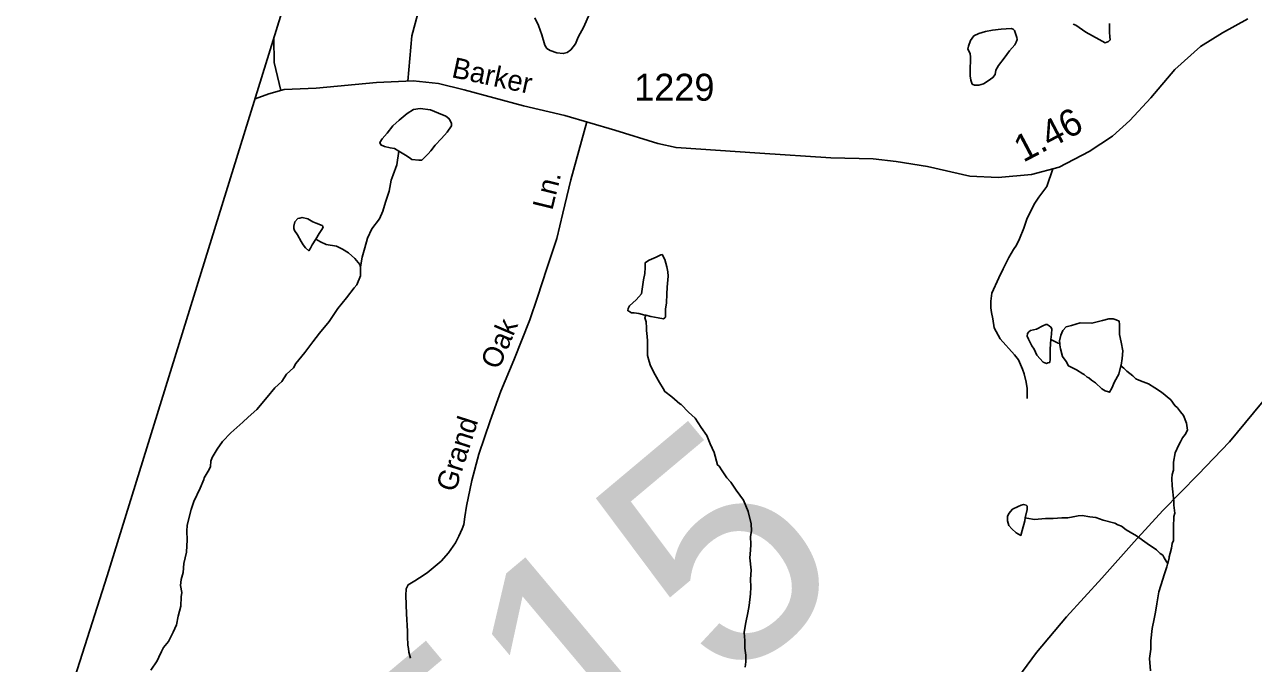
# Model space of a CAD drawing. Extents: x 2001466 to 2224147, y 644118 to 847247.
# Drawn here: x 2010030 to 2015726, y 706438 to 709402 of the extents above; entities that cross this region are included whole.
import ezdxf

# ---------------------------------------------------------------- set-up
doc = ezdxf.new("R2010")
doc.units = 0
for name, color, linetype in [('Exist Boundary Political CountyLine', 7, 'Continuous'), ('Exist Hydrographic Misc Water Feature', 7, 'Continuous'), ('Exist Railroad Mainline', 7, 'Continuous'), ('Exist Road Non-System Type 51', 7, 'Continuous'), ('Exist Road Non-System Type 51 Label', 7, 'Continuous'), ('Exist Road Primary US Structure RailRoad Number Label', 7, 'Continuous'), ('Exist Road Secondary Mileage Hundredths English Label', 7, 'Continuous'), ('Exist Road Secondary Type 51 Attributed', 7, 'Continuous'), ('Exist Road Secondary Type 51 Label', 7, 'Continuous'), ('Exist Road Secondary Type 51 Number Label', 7, 'Continuous')]:
    doc.layers.add(name, color=color, linetype=linetype)

msp = doc.modelspace()

# ---------------------------------------------------------------- linework, layer by layer
at = {"layer": 'Exist Boundary Political CountyLine'}
msp.add_lwpolyline([(2006817.6, 695750.4), (2007499.4, 697710.6), (2010412.6, 706844.6), (2011918.3, 711705.5), (2013748.8, 717730), (2014941.8, 722041.3), (2015284.7, 723238.9), (2015749.8, 724659.3), (2016152.8, 726117.8), (2016501.7, 727373.6), (2016860.6, 728619.5), (2017411.9, 730567.4), (2017756.8, 731851.4), (2018083.6, 732956.8), (2018350.2, 733869.6), (2018833.4, 735584.8), (2018918.2, 735898.3), (2019734.3, 740137.7), (2020502.6, 744108.1), (2021805.5, 746807.9), (2022821.6, 749625), (2023527, 751602.5)], dxfattribs=at)
at = {"layer": 'Exist Hydrographic Misc Water Feature'}
for points in [[(2012394.5, 709432.7), (2012412.5, 709396.7), (2012426.7, 709354.7), (2012440.6, 709306.7), (2012450.7, 709290.7), (2012466.7, 709280.7), (2012496.6, 709270.7), (2012526.7, 709266.7), (2012544.6, 709272.7), (2012562.6, 709284.7), (2012582.7, 709312.8), (2012596.5, 709342.8), (2012622.5, 709390.8), (2012648.5, 709450.8)], [(2014414.4, 709227.9), (2014414.4, 709249.9), (2014412.4, 709267.9), (2014402.3, 709287.9), (2014404.4, 709301.9), (2014414.4, 709327.9), (2014430.4, 709349.9), (2014452.4, 709359.9), (2014484.4, 709370), (2014516.4, 709376), (2014556.3, 709380), (2014602.3, 709384), (2014612.3, 709380), (2014618.3, 709374), (2014624.2, 709356), (2014628.3, 709342.1), (2014630.2, 709332.1), (2014626.5, 709320.1), (2014620.3, 709308.1), (2014594.5, 709280.1), (2014570.3, 709246), (2014544.4, 709212), (2014532.3, 709190), (2014528.5, 709170), (2014518.4, 709156), (2014496.5, 709140), (2014474.5, 709126), (2014452.6, 709120), (2014432.5, 709119.9), (2014422.4, 709125.9), (2014416.5, 709143.9), (2014412.4, 709163.9), (2014412.4, 709181.9), (2014412.4, 709205.9), (2014414.4, 709227.9)], [(2015058.3, 709406.3), (2015058.3, 709380.3), (2015058.3, 709366.3), (2015060.4, 709344.3), (2015062.2, 709330.3), (2015054.2, 709322.3), (2015038.2, 709316.3), (2015010.3, 709332.3), (2014948.2, 709366.3), (2014902.3, 709398.2), (2014890.2, 709404.2)], [(2011765, 708814.4), (2011745.1, 708826.4), (2011725, 708830.3), (2011698.9, 708836.3), (2011681.1, 708844.3), (2011677, 708854.3), (2011686.8, 708872.3), (2011710.8, 708898.3), (2011736.9, 708932.3), (2011766.8, 708958.3), (2011802.9, 708988.4), (2011832.8, 709008.4), (2011863, 709012.4), (2011911, 709006.4), (2011948.9, 708990.4), (2011982.9, 708976.5), (2011996.9, 708966.5), (2012002.8, 708956.5), (2012009, 708942.5), (2012009, 708932.5), (2011988.9, 708902.4), (2011962.8, 708872.5), (2011932.9, 708842.4), (2011913, 708816.5), (2011900.9, 708802.5), (2011883.1, 708784.4), (2011871, 708772.4), (2011857, 708772.4), (2011825, 708776.4), (2011812.9, 708784.4), (2011795.1, 708796.4), (2011765, 708814.4)], [(2011765, 708814.4), (2011754.9, 708750.4), (2011738.9, 708704.4), (2011729.1, 708680.3), (2011719.2, 708628.3), (2011703, 708578.3), (2011691.1, 708536.4), (2011675.2, 708500.3), (2011639.3, 708454.3), (2011619.2, 708410.3), (2011607.3, 708366.3), (2011595.2, 708322.3), (2011587.2, 708278.3)], [(2011379.3, 708406.2), (2011395.3, 708432.2), (2011411.2, 708456.2), (2011413.3, 708464.2), (2011409.2, 708470.2), (2011381.3, 708480.2), (2011365.3, 708486.2), (2011343.2, 708500.1), (2011317.3, 708506.1), (2011305.2, 708504.1), (2011297.2, 708502.1), (2011283.3, 708486.1), (2011277.4, 708466.1), (2011277.4, 708456.1), (2011281.2, 708446.1), (2011295.2, 708426.1), (2011311.2, 708396.1), (2011321.2, 708380.1), (2011331.3, 708366.1), (2011347.3, 708352.2), (2011355.3, 708364.2), (2011363.3, 708380.1), (2011379.3, 708406.2)], [(2011587.2, 708278.3), (2011583.3, 708288.3), (2011561.3, 708316.2), (2011531.2, 708342.2), (2011503.3, 708360.3), (2011475.2, 708374.3), (2011427.2, 708382.2), (2011401.2, 708394.2), (2011379.3, 708406.2)], [(2012909.2, 708053.1), (2012905.3, 708053.1), (2012877.2, 708061.1), (2012855.2, 708065.1), (2012843.3, 708065.1), (2012835.3, 708069.1), (2012825.3, 708075.1), (2012827.1, 708085.1), (2012833.3, 708097.1), (2012865.3, 708125.1), (2012889.3, 708153.2), (2012899.1, 708217.1), (2012905.1, 708247.1), (2012907.1, 708275.2), (2012907.1, 708297.1), (2012913.1, 708301.1), (2012925.1, 708309.2), (2012957.1, 708323.2), (2012973.1, 708331.1), (2012979.1, 708333.1), (2012985, 708335.1), (2012997.1, 708311.2), (2013007.2, 708277.2), (2013011.1, 708255.2), (2013013.1, 708235.2), (2013009, 708183.2), (2013007.2, 708151.2), (2013005.3, 708111.2), (2013001.2, 708081.2), (2013001.2, 708067.2), (2013001.2, 708045.2), (2012997.3, 708041.2), (2012991.2, 708037.2), (2012967.2, 708041.2), (2012933.1, 708047.2), (2012909.2, 708053.1)], [(2011587.2, 708278.3), (2011587.4, 708236.3), (2011569.3, 708194.3), (2011557.5, 708180.3), (2011521.4, 708134.3), (2011481.6, 708084.3), (2011441.6, 708024.2), (2011397.5, 707970.3), (2011365.5, 707930.2), (2011329.6, 707880.2), (2011301.5, 707846.2), (2011287.6, 707830.2), (2011275.7, 707810.2), (2011243.5, 707780.1), (2011221.6, 707746.1), (2011189.8, 707716.1), (2011153.7, 707674.1), (2011105.7, 707616.1), (2011065.7, 707580), (2011041.7, 707558.1), (2010985.8, 707508.1), (2010947.8, 707468), (2010921.8, 707432), (2010899.8, 707394), (2010893.9, 707376), (2010891.9, 707352), (2010885.9, 707338), (2010861.9, 707300), (2010860.1, 707292), (2010844.1, 707252), (2010813.9, 707189.9), (2010802, 707152), (2010784.2, 707079.9), (2010782.1, 707052), (2010784, 707012), (2010780.3, 706954), (2010768.2, 706902), (2010764.3, 706860), (2010756.3, 706828), (2010752.2, 706800), (2010758.2, 706768), (2010756.3, 706748), (2010754.3, 706704), (2010742.4, 706658), (2010734.4, 706618), (2010718.4, 706584), (2010696.4, 706540), (2010674.5, 706512), (2010664.4, 706493.9), (2010652.6, 706467.9), (2010644.4, 706449.9), (2010614.4, 706407.9)], [(2013370.1, 706421.7), (2013372.2, 706445.6), (2013372.2, 706477.6), (2013368.1, 706509.6), (2013368.1, 706545.6), (2013366, 706581.6), (2013368.1, 706601.6), (2013372.2, 706627.6), (2013382, 706673.6), (2013388, 706707.6), (2013393.9, 706761.6), (2013395.9, 706791.6), (2013393.9, 706829.6), (2013398, 706871.6), (2013391.8, 706927.6), (2013393.9, 706963.6), (2013395.7, 706989.6), (2013393.9, 707027.6), (2013399.8, 707053.6), (2013397.8, 707085.5), (2013383.6, 707143.5), (2013361.7, 707195.5), (2013327.7, 707241.4), (2013303.7, 707279.4), (2013285.6, 707299.5), (2013263.5, 707331.5), (2013249.5, 707353.4), (2013241.5, 707359.4), (2013225.6, 707417.4), (2013207.5, 707457.4), (2013191.5, 707495.4), (2013165.7, 707533.4), (2013137.4, 707575.3), (2013107.4, 707603.3), (2013073.4, 707639.3), (2013067.5, 707643.2), (2013029.5, 707675.3), (2012997.5, 707699.3), (2012989.5, 707713.2), (2012973.5, 707741.2), (2012953.4, 707777.2), (2012931.3, 707819.2), (2012925.4, 707839.1), (2012917.4, 707867.2), (2012917.4, 707899.2), (2012917.4, 707935.1), (2012915.3, 707955.1), (2012913.3, 707983.1), (2012913.3, 707995.1), (2012911.2, 708023.2), (2012905.3, 708041.2), (2012909.2, 708053.1)], [(2014787, 707940.3), (2014785.2, 707920.3), (2014783.1, 707894.3), (2014783.1, 707850.3), (2014781.3, 707834.3), (2014773.1, 707832.3), (2014767.1, 707830.3), (2014751.1, 707836.3), (2014721.2, 707868.2), (2014709.1, 707896.2), (2014699.1, 707912.2), (2014689, 707930.2), (2014683.1, 707942.2), (2014677.1, 707956.3), (2014679.2, 707968.3), (2014685.1, 707976.3), (2014693.1, 707982.3), (2014721, 707988.2), (2014749.1, 708004.3), (2014763, 708010.3), (2014769.2, 708010.3), (2014779, 708004.3), (2014787, 707998.3), (2014791.1, 707990.3), (2014789.1, 707966.3), (2014787, 707940.3)], [(2015111, 707818.5), (2015113.1, 707822.5), (2015117.2, 707852.5), (2015121.1, 707888.5), (2015113.1, 707928.5), (2015105.1, 707964.5), (2015105.1, 708010.5), (2015103, 708026.5), (2015089.1, 708032.5), (2015074.9, 708036.4), (2015055, 708036.4), (2015026.9, 708028.4), (2014976.9, 708016.4), (2014923, 708018.4), (2014883.2, 708006.3), (2014857.1, 708000.3), (2014843, 707982.3), (2014833.2, 707960.4), (2014827, 707934.3), (2014829.1, 707922.3)], [(2014787, 707940.3), (2014821.1, 707924.3), (2014829.1, 707922.3)], [(2014829.1, 707922.3), (2014829.1, 707916.3), (2014831.1, 707898.4), (2014841.2, 707862.3), (2014857.1, 707838.4), (2014869.2, 707818.4), (2014905.1, 707800.4), (2014935.3, 707782.4), (2014941.2, 707778.4), (2014955.2, 707766.4), (2014963.2, 707762.4), (2014975.3, 707752.4), (2014993.3, 707740.5), (2015023.2, 707712.5), (2015039.2, 707702.5), (2015053.2, 707698.5), (2015059.1, 707696.5), (2015069.2, 707714.5), (2015081.3, 707744.5), (2015101.2, 707780.5), (2015111, 707818.5)], [(2015327.7, 706898.8), (2015328.6, 706902), (2015335.5, 706928.7), (2015335.5, 706932.7), (2015339.6, 706950.7), (2015345.6, 706972.7), (2015349.5, 706994.8), (2015355.6, 707008.8), (2015355.6, 707034.8), (2015355.6, 707070.7), (2015357.5, 707120.7), (2015361.4, 707134.8), (2015357.5, 707172.8), (2015357.5, 707190.8), (2015349.5, 707262.7), (2015347.4, 707296.8), (2015349.3, 707314.8), (2015355.2, 707334.7), (2015355.2, 707372.7), (2015363.4, 707414.8), (2015379.4, 707452.8), (2015387.4, 707466.8), (2015397.3, 707484.7), (2015409.4, 707500.7), (2015419.4, 707520.7), (2015415.3, 707552.8), (2015401.2, 707588.8), (2015387.2, 707604.7), (2015373.3, 707624.7), (2015361.2, 707634.7), (2015343.1, 707660.7), (2015299.2, 707696.7), (2015269.3, 707716.6), (2015239.2, 707734.6), (2015215.2, 707744.6), (2015195.1, 707752.6), (2015181.1, 707758.5), (2015167, 707772.5), (2015139.1, 707794.6), (2015125.2, 707808.5), (2015111, 707818.5)], [(2014667.5, 707114.4), (2014665.6, 707100.3), (2014653.5, 707054.3), (2014647.6, 707032.3), (2014625.6, 707044.3), (2014605.6, 707062.3), (2014591.6, 707078.3), (2014585.7, 707100.3), (2014585.7, 707120.3), (2014591.6, 707134.3), (2014609.7, 707154.3), (2014635.5, 707166.3), (2014649.6, 707172.3), (2014659.5, 707176.3), (2014671.6, 707172.3), (2014677.5, 707168.3), (2014677.5, 707152.3), (2014667.5, 707114.4)], [(2014667.5, 707114.4), (2014675.5, 707112.4), (2014711.6, 707106.4), (2014761.6, 707110.4), (2014797.5, 707110.4), (2014837.7, 707114.4), (2014865.6, 707114.5), (2014889.5, 707118.5), (2014913.5, 707122.5), (2014931.6, 707124.5), (2014967.5, 707118.6), (2014995.6, 707114.6), (2015029.6, 707102.6), (2015083.5, 707088.6), (2015097.5, 707080.6), (2015113.5, 707074.6), (2015135.6, 707058.6), (2015153.7, 707046.7), (2015183.6, 707030.7), (2015233.6, 706994.7), (2015275.7, 706964.7), (2015293.5, 706948.7), (2015305.6, 706940.7), (2015311.5, 706928.7), (2015321.6, 706912.8), (2015328.6, 706902), (2015327.7, 706898.8)], [(2015248, 706404.8), (2015243.9, 706460.8), (2015249.8, 706504.7), (2015249.8, 706542.7), (2015255.8, 706600.8), (2015265.8, 706644.7), (2015271.8, 706676.7), (2015277.7, 706714.7), (2015287.8, 706770.8), (2015305.6, 706828.7), (2015311.8, 706848.7), (2015323.6, 706886.8), (2015327.7, 706898.8)]]:
    msp.add_lwpolyline(points, dxfattribs=at)
at = {"layer": 'Exist Railroad Mainline'}
msp.add_lwpolyline([(2014572.7, 706290.1), (2014720, 706488.5), (2014859.4, 706655.1), (2015022.8, 706833.8), (2015172.3, 707002.1), (2015305.7, 707148.6), (2015469.1, 707315.3), (2015614.6, 707465.8), (2015881.4, 707788.8)], dxfattribs=at)
at = {"layer": 'Exist Road Non-System Type 51'}
for points in [[(2011807, 709139.6), (2011824.8, 709349), (2011850.5, 709447.5), (2011893.7, 709578.5), (2011954, 709682.3), (2012040.9, 709792.7), (2012589.5, 710385.2)], [(2011217.1, 709096.4), (2011187.1, 709225.8), (2011184.6, 709336.9)], [(2012635.3, 708950.2), (2012561.7, 708681), (2012524, 708527), (2012496.4, 708408.9), (2012450.8, 708270.8), (2012407, 708136.7), (2012372, 708032.4), (2012297.2, 707845.3), (2012237.3, 707700.6), (2012187.5, 707563.4), (2012135.1, 707408.7), (2012102.7, 707287.7), (2012077.8, 707167.9), (2012070.3, 707118), (2012065.3, 707083.1), (2012057.8, 707063.1), (2012042.9, 707028.2), (2012027.9, 706998.3), (2011995.5, 706950.9), (2011960.6, 706913.4), (2011895.7, 706858.5), (2011860.8, 706836.1), (2011838.4, 706821.1), (2011808.4, 706803.2), (2011798.4, 706785.2), (2011796.6, 706753.2), (2011800.6, 706669.3), (2011805.2, 706588.8), (2011805.1, 706563.2), (2011806.3, 706523.4), (2011809.7, 706507.1), (2011811.2, 706491.3), (2011819.2, 706463.3)], [(2014796.2, 708732.3), (2014767.8, 708651.2), (2014731.6, 708600.5), (2014709.9, 708569.1), (2014675.1, 708499.5), (2014661.2, 708457.7), (2014640.9, 708407.3), (2014628, 708378.4), (2014613, 708358.1), (2014591.6, 708321.6), (2014565.1, 708269.3), (2014545.6, 708226.3), (2014513.5, 708155.6), (2014509.2, 708118.1), (2014509.2, 708088.1), (2014512.4, 708066.7), (2014517.8, 708036.7), (2014523.9, 707995.2), (2014552, 707943.3), (2014618.4, 707869.4), (2014636.6, 707846.9), (2014655.9, 707804), (2014662.3, 707781.5), (2014671.9, 707743), (2014676.2, 707713), (2014677.3, 707666.9)]]:
    msp.add_lwpolyline(points, dxfattribs=at)
at = {"layer": 'Exist Road Secondary Type 51 Attributed'}
msp.add_lwpolyline([(2015699.2, 709428.1), (2015582.7, 709362.6), (2015480.6, 709300.4), (2015361.3, 709192.6), (2015250.4, 709062.5), (2015153.1, 708957.1), (2015071.8, 708883.7), (2014964.9, 708813.4), (2014825.7, 708740), (2014696.4, 708706.5), (2014543.3, 708692.1), (2014410.9, 708698.5), (2014214.6, 708743.2), (2014069.8, 708767.1), (2013962.9, 708778.3), (2013767.5, 708783.1), (2013438, 708805.5), (2013049.9, 708831), (2012964.6, 708849.4), (2012765.2, 708911.6), (2012533.8, 708980.3), (2012342.4, 709025), (2012066.8, 709099.2), (2011948.7, 709128), (2011830.6, 709140.7), (2011661.5, 709132.7), (2011380.7, 709107.2), (2011232.8, 709100.8), (2011161.8, 709080.9), (2011098.2, 709057.9)], dxfattribs=at)

# ---------------------------------------------------------------- texts
at = {"layer": 'Exist Road Non-System Type 51 Label'}
for s, rotation, p in [('Ln.', 76.232, (2012475.7, 708536.8)), ('Oak', 66.8812, (2012227.5, 707796.8)), ('Grand', 72.1671, (2012025.7, 707228.6))]:
    msp.add_text(s, height=95, rotation=rotation, dxfattribs=at).set_placement(p)
at = {"layer": 'Exist Road Primary US Structure RailRoad Number Label'}
msp.add_text('R515', height=1066.27, rotation=40, dxfattribs=at).set_placement((2011268.8, 704630.6))
at = {"layer": 'Exist Road Secondary Mileage Hundredths English Label'}
msp.add_text('1.46', height=125, rotation=27.8154, dxfattribs=at).set_placement((2014658.6, 708760))
at = {"layer": 'Exist Road Secondary Type 51 Label'}
msp.add_text('Barker', height=95, rotation=347.8794, dxfattribs=at).set_placement((2012005.2, 709158.1))
at = {"layer": 'Exist Road Secondary Type 51 Number Label'}
msp.add_text('1229', height=125, dxfattribs=at).set_placement((2012855.7, 709048.5))

doc.saveas('drawing.dxf')
